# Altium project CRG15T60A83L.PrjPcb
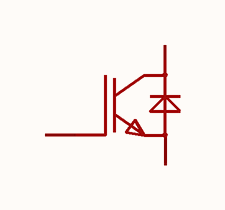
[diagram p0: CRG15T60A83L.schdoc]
1 sheet, 1 parts. Net scope: global (net labels, ports and power ports of the same name join across sheets).

## Sheet CRG15T60A83L.schdoc
size 127 x 101 mm

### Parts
Q?  crg15t60a83l  [TO-220-3_L10.0-W4.5-P2.54-L-1]  (value not drawn)

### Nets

Not connected (* = marked no-connect by the designer): Q? 1(G) 2(C) 3(E)

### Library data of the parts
Q? = crg15t60a83l: IGBT类型:-;耗散功率(Pd):96W;集射极击穿电压(Vces):600V;集电极电流(Ic):15A;; Manufacturer: CRMICRO(华润微); AddInBom: yes; ModelId: f3b81a431813461aaa6f5a84087f9609; ModelTransform: 393.7,177.5587,0,0,0,0,0,16.417,-196.85; Pd - Power Dissipation: 96W; Collector-Emitter Breakdown Voltage (Vces): 600V; Current - Collector(Ic): 15A; Current - Collector Pulsed (Icm): 45A; Vce Saturation(VCE(sat)): 2.4V@15A,15V; Gate-Emitter Threshold Voltage (Vge(th)@Ic): 4.5V@250uA; Gate Charge(Qg): 59nC@15V; Input Capacitance(Cies): 1.095nF; Output Capacitance(Coes): 60pF; Reverse Transfer Capacitance (Cres): 32pF; Td(on): 30ns; Td(off): 45ns; Turn-On Energy (Eon): 600uJ; Switching Energy(Eoff): 190uJ; Reverse Recovery Time(trr): 47ns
